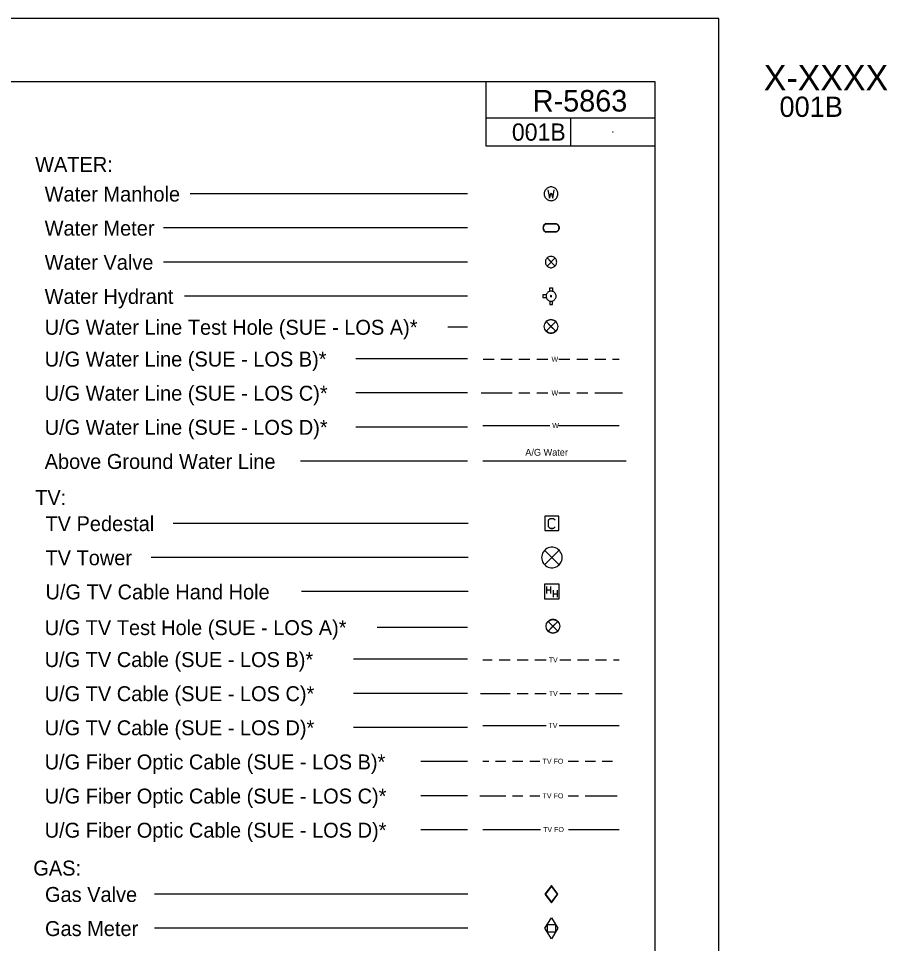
# Model space of a CAD drawing. Extents: x 2040834 to 2047174, y 618431 to 621625.
# Drawn here: x 2046575 to 2047174, y 620986 to 621625 of the extents above; entities that cross this region are included whole.
import ezdxf

# ---------------------------------------------------------------- set-up
doc = ezdxf.new("R2010")
doc.units = 0
for name, color, linetype in [('Default', 7, 'Continuous'), ('Exist Utilities TV Test Hole SUE LOS A CELL', 7, 'Continuous'), ('Exist Utilities Water Test Hole SUE LOS A CELL', 7, 'Continuous')]:
    doc.layers.add(name, color=color, linetype=linetype)

msp = doc.modelspace()

# ---------------------------------------------------------------- linework, layer by layer
at = {"layer": 'Default'}
for p, q in [((2047057.71, 621624.54), (2045074.38, 621624.54)), ((2047057.71, 620341.21), (2047057.71, 621624.54)), ((2047013.96, 621580.79), (2045118.13, 621580.79)), ((2046897.29, 621536.55), (2046897.3, 621580.79)), ((2047013.93, 620384.96), (2047013.96, 621580.79)), ((2047013.96, 621555.8), (2046897.29, 621555.8)), ((2046955.63, 621536.55), (2046955.63, 621555.8)), ((2047013.96, 621536.55), (2046897.29, 621536.55)), ((2046884.38, 621503.62), (2046693.23, 621503.62)), ((2046884.38, 621480.08), (2046674.81, 621480.08)), ((2046938.48, 621483.11), (2046945.71, 621483.11)), ((2046938.48, 621482.87), (2046945.71, 621482.87)), ((2046945.66, 621477.34), (2046938.48, 621477.34)), ((2046945.66, 621477.1), (2046938.48, 621477.1)), ((2046884.38, 621456.54), (2046674.81, 621456.54)), ((2046884.38, 621433), (2046689.23, 621433)), ((2046884.38, 621411.71), (2046870.79, 621411.71)), ((2046884.38, 621389.76), (2046807.42, 621389.76)), ((2046895.18, 621389.51), (2046902.83, 621389.51)), ((2046907.54, 621389.51), (2046915.19, 621389.51)), ((2046919.9, 621389.51), (2046927.55, 621389.51)), ((2046932.26, 621389.51), (2046939.91, 621389.51)), ((2046947.44, 621389.51), (2046955.09, 621389.51)), ((2046959.8, 621389.51), (2046967.45, 621389.51)), ((2046972.16, 621389.51), (2046979.81, 621389.51)), ((2046984.52, 621389.51), (2046989.15, 621389.51)), ((2046884.38, 621366.22), (2046807.42, 621366.22)), ((2046893.84, 621366.22), (2046915.19, 621366.22)), ((2046919.9, 621366.22), (2046927.55, 621366.22)), ((2046932.26, 621366.22), (2046939.91, 621366.22)), ((2046947.44, 621366.22), (2046955.09, 621366.22)), ((2046959.8, 621366.22), (2046967.45, 621366.22)), ((2046972.16, 621366.22), (2046991.36, 621366.22)), ((2046884.38, 621342.68), (2046807.42, 621342.68)), ((2046894.99, 621343.71), (2046941.25, 621343.71)), ((2046947.13, 621343.71), (2046989.15, 621343.71)), ((2046884.38, 621319.14), (2046769.36, 621319.14)), ((2046894.99, 621319.39), (2046993.88, 621319.39)), ((2046884.94, 621276.24), (2046681.4, 621276.24)), ((2046941.89, 621272.77), (2046943.41, 621272.77)), ((2046884.94, 621252.7), (2046666.19, 621252.7)), ((2046884.94, 621229.15), (2046769.92, 621229.15)), ((2046939.03, 621232.72), (2046939.03, 621227.97)), ((2046939.03, 621230.3), (2046941.74, 621230.3)), ((2046941.74, 621232.72), (2046941.74, 621227.97)), ((2046943.55, 621230.13), (2046943.55, 621225.39)), ((2046946.26, 621230.13), (2046946.26, 621225.39)), ((2046943.55, 621227.72), (2046946.26, 621227.72)), ((2046884.38, 621204.51), (2046822.16, 621204.51)), ((2046884.38, 621182.48), (2046805.88, 621182.48)), ((2046894.99, 621182.1), (2046901.55, 621182.1)), ((2046906.26, 621182.1), (2046913.91, 621182.1)), ((2046918.62, 621182.1), (2046926.27, 621182.1)), ((2046930.98, 621182.1), (2046938.63, 621182.1)), ((2046948.04, 621182.1), (2046955.7, 621182.1)), ((2046960.4, 621182.1), (2046968.06, 621182.1)), ((2046972.76, 621182.1), (2046980.41, 621182.1)), ((2046985.12, 621182.1), (2046989.15, 621182.1)), ((2046884.38, 621158.94), (2046805.88, 621158.94)), ((2046893.36, 621158.94), (2046913.91, 621158.94)), ((2046918.62, 621158.94), (2046926.27, 621158.94)), ((2046930.98, 621158.94), (2046938.63, 621158.94)), ((2046948.04, 621158.94), (2046955.7, 621158.94)), ((2046960.4, 621158.94), (2046968.06, 621158.94)), ((2046972.76, 621158.94), (2046991.13, 621158.94)), ((2046884.38, 621135.4), (2046805.88, 621135.4)), ((2046894.99, 621136.83), (2046938.75, 621136.83)), ((2046947.57, 621136.83), (2046989.15, 621136.83)), ((2046884.38, 621111.86), (2046852.32, 621111.86)), ((2046894.99, 621112.14), (2046899.11, 621112.14)), ((2046903.82, 621112.14), (2046910.88, 621112.14)), ((2046915.59, 621112.14), (2046922.65, 621112.14)), ((2046927.36, 621112.14), (2046934.42, 621112.14)), ((2046953.84, 621112.14), (2046960.9, 621112.14)), ((2046965.61, 621112.14), (2046972.68, 621112.14)), ((2046977.38, 621112.14), (2046984.45, 621112.14)), ((2046884.38, 621088.32), (2046852.32, 621088.32)), ((2046893.06, 621088.32), (2046910.88, 621088.32)), ((2046915.59, 621088.32), (2046922.65, 621088.32)), ((2046927.36, 621088.32), (2046934.42, 621088.32)), ((2046953.84, 621088.32), (2046960.9, 621088.32)), ((2046965.61, 621088.32), (2046987.66, 621088.32)), ((2046884.38, 621064.77), (2046852.32, 621064.77)), ((2046894.99, 621065.05), (2046934.76, 621065.05)), ((2046954.18, 621065.05), (2046989.15, 621065.05)), ((2046942.31, 621025.99), (2046938.18, 621020.44)), ((2046946.45, 621020.44), (2046942.31, 621025.99)), ((2046884.62, 621020.44), (2046668.64, 621020.44)), ((2046938.18, 621020.44), (2046942.31, 621014.88)), ((2046942.31, 621014.88), (2046946.45, 621020.44)), ((2046884.62, 620996.89), (2046668.64, 620996.89))]:
    msp.add_line(p, q, dxfattribs=at)
for points in [[(2046942.07, 621508.4), (2046941.46, 621508.37), (2046940.89, 621508.25), (2046940.31, 621508.06), (2046939.78, 621507.79), (2046939.28, 621507.49), (2046938.82, 621507.1), (2046938.4, 621506.65), (2046938.06, 621506.19), (2046937.75, 621505.65), (2046937.56, 621505.08), (2046937.41, 621504.5), (2046937.33, 621503.93), (2046937.33, 621503.32), (2046937.41, 621502.75), (2046937.56, 621502.13), (2046937.75, 621501.6), (2046938.06, 621501.06), (2046938.4, 621500.6), (2046938.82, 621500.15), (2046939.28, 621499.76), (2046939.78, 621499.46), (2046940.31, 621499.19), (2046940.89, 621499), (2046941.5, 621498.88), (2046942.07, 621498.85), (2046942.68, 621498.88), (2046943.26, 621499), (2046943.83, 621499.19), (2046944.36, 621499.46), (2046944.86, 621499.76), (2046945.32, 621500.15), (2046945.74, 621500.6), (2046946.09, 621501.06), (2046946.39, 621501.6), (2046946.58, 621502.17), (2046946.74, 621502.75), (2046946.81, 621503.32), (2046946.81, 621503.93), (2046946.74, 621504.5), (2046946.58, 621505.11), (2046946.39, 621505.65), (2046946.09, 621506.19), (2046945.74, 621506.65), (2046945.32, 621507.1), (2046944.86, 621507.49), (2046944.36, 621507.79), (2046943.83, 621508.06), (2046943.26, 621508.25), (2046942.64, 621508.37), (2046942.07, 621508.4)], [(2046939.93, 621506.26), (2046940.92, 621500.68), (2046942.07, 621504.2), (2046943.26, 621500.68), (2046944.25, 621506.26)], [(2046938.48, 621483.11), (2046938.01, 621482.87), (2046937.58, 621482.54), (2046937.2, 621482.12), (2046936.92, 621481.69), (2046936.68, 621481.17), (2046936.54, 621480.65), (2046936.49, 621480.13), (2046936.54, 621479.56), (2046936.68, 621479.04), (2046936.92, 621478.57), (2046937.2, 621478.1), (2046937.58, 621477.72), (2046938.01, 621477.39), (2046938.48, 621477.1)], [(2046938.57, 621482.92), (2046938.1, 621482.64), (2046937.68, 621482.3), (2046937.3, 621481.88), (2046937.01, 621481.45), (2046936.82, 621480.93), (2046936.73, 621480.37), (2046936.73, 621479.85), (2046936.82, 621479.33), (2046937.01, 621478.81), (2046937.3, 621478.33), (2046937.68, 621477.91), (2046938.1, 621477.58), (2046938.57, 621477.34)], [(2046945.57, 621482.92), (2046946.09, 621482.68), (2046946.51, 621482.3), (2046946.84, 621481.93), (2046947.13, 621481.45), (2046947.32, 621480.93), (2046947.41, 621480.37), (2046947.41, 621479.85), (2046947.32, 621479.28), (2046947.13, 621478.81), (2046946.84, 621478.33), (2046946.47, 621477.91), (2046946.04, 621477.58), (2046945.57, 621477.29)], [(2046945.66, 621483.11), (2046946.14, 621482.87), (2046946.56, 621482.54), (2046946.94, 621482.12), (2046947.22, 621481.69), (2046947.46, 621481.17), (2046947.6, 621480.65), (2046947.65, 621480.13), (2046947.6, 621479.56), (2046947.46, 621479.04), (2046947.22, 621478.57), (2046946.94, 621478.1), (2046946.56, 621477.72), (2046946.14, 621477.39), (2046945.66, 621477.1)], [(2046945.98, 621456.54), (2046945.94, 621457.11), (2046945.81, 621457.71), (2046945.59, 621458.23), (2046945.29, 621458.76), (2046944.94, 621459.19), (2046944.5, 621459.58), (2046944.03, 621459.93), (2046943.5, 621460.19), (2046942.94, 621460.37), (2046942.38, 621460.45), (2046941.77, 621460.45), (2046941.2, 621460.37), (2046940.64, 621460.19), (2046940.11, 621459.93), (2046939.64, 621459.58), (2046939.2, 621459.19), (2046938.86, 621458.76), (2046938.55, 621458.23), (2046938.33, 621457.71), (2046938.2, 621457.11), (2046938.16, 621456.54), (2046938.2, 621455.98), (2046938.33, 621455.37), (2046938.55, 621454.85), (2046938.86, 621454.33), (2046939.2, 621453.89), (2046939.64, 621453.5), (2046940.11, 621453.15), (2046940.64, 621452.89), (2046941.2, 621452.72), (2046941.77, 621452.63), (2046942.38, 621452.63), (2046942.94, 621452.72), (2046943.5, 621452.89), (2046944.03, 621453.15), (2046944.5, 621453.5), (2046944.94, 621453.89), (2046945.29, 621454.33), (2046945.59, 621454.85), (2046945.81, 621455.37), (2046945.94, 621455.98), (2046945.98, 621456.54)], [(2046944.85, 621453.76), (2046939.29, 621459.32), (2046942.07, 621456.54), (2046939.29, 621453.76), (2046944.85, 621459.32)], [(2046938.73, 621433.9), (2046936.47, 621433.9), (2046936.47, 621432.1), (2046938.73, 621432.1)], [(2046942.03, 621436.48), (2046941.48, 621436.43), (2046940.94, 621436.3), (2046940.4, 621436.07), (2046939.95, 621435.76), (2046939.54, 621435.39), (2046939.18, 621434.94), (2046938.91, 621434.45), (2046938.73, 621433.9), (2046938.59, 621433.36), (2046938.59, 621432.82), (2046938.68, 621432.28), (2046938.82, 621431.73), (2046939.09, 621431.24), (2046939.4, 621430.79), (2046939.81, 621430.38), (2046940.26, 621430.02), (2046940.76, 621429.79), (2046941.3, 621429.61), (2046941.85, 621429.52), (2046942.39, 621429.52), (2046942.93, 621429.61), (2046943.47, 621429.84), (2046943.97, 621430.06), (2046944.42, 621430.42), (2046944.78, 621430.83), (2046945.1, 621431.28), (2046945.32, 621431.82), (2046945.5, 621432.37), (2046945.55, 621432.91), (2046945.5, 621433.45), (2046945.41, 621433.99), (2046945.19, 621434.54), (2046944.92, 621435.03), (2046944.56, 621435.44), (2046944.11, 621435.8), (2046943.65, 621436.12), (2046943.11, 621436.3), (2046942.57, 621436.43), (2046942.03, 621436.48)], [(2046941.21, 621436.39), (2046941.21, 621438.65), (2046943.02, 621438.65), (2046943.02, 621436.34)], [(2046942.07, 621433.41), (2046941.89, 621433.36), (2046941.75, 621433.22), (2046941.66, 621433.04), (2046941.71, 621432.86), (2046941.8, 621432.68), (2046941.98, 621432.59), (2046942.16, 621432.59), (2046942.34, 621432.68), (2046942.43, 621432.86), (2046942.48, 621433.04), (2046942.39, 621433.22), (2046942.25, 621433.36), (2046942.07, 621433.41)], [(2046941.21, 621429.61), (2046941.21, 621427.35), (2046943.02, 621427.35), (2046943.02, 621429.66)], [(2046937.73, 621271.33), (2046947.54, 621271.33), (2046947.54, 621281.14), (2046937.73, 621281.14), (2046937.73, 621271.33)], [(2046944.93, 621273.86), (2046943.76, 621272.77), (2046941.5, 621272.77), (2046940.42, 621273.86), (2046940.42, 621278.61), (2046941.5, 621279.7), (2046943.76, 621279.7), (2046944.93, 621278.61)], [(2046949.72, 621252.7), (2046949.64, 621253.72), (2046949.41, 621254.82), (2046949.01, 621255.77), (2046948.46, 621256.71), (2046947.83, 621257.5), (2046947.05, 621258.21), (2046946.18, 621258.84), (2046945.23, 621259.31), (2046944.21, 621259.63), (2046943.19, 621259.79), (2046942.08, 621259.79), (2046941.06, 621259.63), (2046940.03, 621259.31), (2046939.09, 621258.84), (2046938.22, 621258.21), (2046937.44, 621257.5), (2046936.81, 621256.71), (2046936.25, 621255.77), (2046935.86, 621254.82), (2046935.62, 621253.72), (2046935.54, 621252.7), (2046935.62, 621251.67), (2046935.86, 621250.57), (2046936.25, 621249.63), (2046936.81, 621248.68), (2046937.44, 621247.89), (2046938.22, 621247.18), (2046939.09, 621246.55), (2046940.03, 621246.08), (2046941.06, 621245.76), (2046942.08, 621245.61), (2046943.19, 621245.61), (2046944.21, 621245.76), (2046945.23, 621246.08), (2046946.18, 621246.55), (2046947.05, 621247.18), (2046947.83, 621247.89), (2046948.46, 621248.68), (2046949.01, 621249.63), (2046949.41, 621250.57), (2046949.64, 621251.67), (2046949.72, 621252.7)], [(2046947.68, 621247.65), (2046937.59, 621257.74), (2046942.63, 621252.7), (2046937.59, 621247.65), (2046947.68, 621257.74)], [(2046937.57, 621224.09), (2046947.7, 621224.09), (2046947.7, 621234.22), (2046937.57, 621234.22), (2046937.57, 621224.09)], [(2046942.31, 621026.46), (2046937.82, 621020.44), (2046942.31, 621014.41), (2046946.8, 621020.44), (2046942.31, 621026.46)], [(2046937.82, 620996.89), (2046942.31, 621004.16), (2046946.8, 620996.89), (2046942.31, 620989.63), (2046937.82, 620996.89)], [(2046939.53, 620999.61), (2046945.09, 620999.61), (2046945.09, 620994.12), (2046939.53, 620994.12), (2046939.53, 620999.61)]]:
    msp.add_lwpolyline(points, dxfattribs=at)
for centre in [(2046955.63, 621568.3), (2046926.46, 621546.18), (2046984.79, 621546.18), (2046897.29, 621536.55)]:
    msp.add_circle(centre, 0.07, dxfattribs=at)
at = {"layer": 'Exist Utilities TV Test Hole SUE LOS A CELL'}
for points in [[(2046946.7, 621208.58), (2046940.05, 621201.93), (2046943.37, 621205.25), (2046940.05, 621208.58), (2046946.7, 621201.93)], [(2046940.05, 621208.58), (2046943.37, 621205.25), (2046946.7, 621208.58)], [(2046946.7, 621201.93), (2046943.37, 621205.25), (2046940.05, 621201.93)]]:
    msp.add_lwpolyline(points, dxfattribs=at)
msp.add_circle((2046943.37, 621205.25), 4.7, dxfattribs=at)
for start, end in [(45, 135), (225, 315)]:
    msp.add_arc((2046943.37, 621205.25), 4.7, start, end, dxfattribs=at)
at = {"layer": 'Exist Utilities Water Test Hole SUE LOS A CELL'}
for points in [[(2046945.36, 621415.45), (2046938.7, 621408.8), (2046942.03, 621412.12), (2046938.7, 621415.45), (2046945.36, 621408.8)], [(2046938.7, 621415.45), (2046942.03, 621412.12), (2046945.36, 621415.45)], [(2046945.36, 621408.8), (2046942.03, 621412.12), (2046938.7, 621408.8)]]:
    msp.add_lwpolyline(points, dxfattribs=at)
msp.add_circle((2046942.03, 621412.12), 4.7, dxfattribs=at)
for start, end in [(45, 135), (225, 315)]:
    msp.add_arc((2046942.03, 621412.12), 4.7, start, end, dxfattribs=at)

# ---------------------------------------------------------------- texts
at = {"layer": 'Default'}
for s, height, p in [('X-XXXX', 17.5, (2047088.78, 621574.97)), ('R-5863', 14.859, (2046929.46, 621560.34)), ('001B', 14, (2047099.63, 621556.66)), ('001B', 11.887, (2046915.05, 621540.25)), ('WATER:', 10.3, (2046586.25, 621518.74)), ('Water Manhole', 10.2996, (2046592.81, 621498.28)), ('Water Meter', 10.2996, (2046592.81, 621474.74)), ('Water Valve', 10.2996, (2046592.81, 621451.2)), ('Water Hydrant', 10.2996, (2046592.81, 621427.66)), ('U/G Water Line Test Hole (SUE - LOS A)*', 10.2996, (2046592.81, 621406.37)), ('U/G Water Line (SUE - LOS B)*', 10.2996, (2046592.81, 621384.42)), ('W', 3.53, (2046942.38, 621387.74)), ('U/G Water Line (SUE - LOS C)*', 10.2996, (2046592.81, 621360.88)), ('W', 3.53, (2046942.38, 621364.45)), ('U/G Water Line (SUE - LOS D)*', 10.2996, (2046592.81, 621337.34)), ('W', 3.53, (2046942.89, 621341.95)), ('Above Ground Water Line', 10.2996, (2046592.81, 621313.8)), ('A/G Water', 4.708, (2046924.33, 621322.92)), ('TV:', 10.3, (2046586.25, 621288.89)), ('TV Pedestal', 10.2996, (2046593.37, 621270.9)), ('TV Tower', 10.3, (2046593.37, 621247.36)), ('U/G TV Cable Hand Hole', 10.2996, (2046593.37, 621223.81)), ('U/G TV Test Hole (SUE - LOS A)*', 10.2996, (2046592.81, 621199.17)), ('U/G TV Cable (SUE - LOS B)*', 10.2996, (2046592.81, 621177.14)), ('TV', 3.531, (2046940.45, 621180.34)), ('U/G TV Cable (SUE - LOS C)*', 10.2996, (2046592.81, 621153.6)), ('TV', 3.531, (2046940.45, 621157.18)), ('U/G TV Cable (SUE - LOS D)*', 10.2996, (2046592.81, 621130.06)), ('TV', 3.531, (2046940.28, 621135.06)), ('U/G Fiber Optic Cable (SUE - LOS B)*', 10.2996, (2046592.81, 621106.52)), ('TV FO', 3.531, (2046936.24, 621110.38)), ('U/G Fiber Optic Cable (SUE - LOS C)*', 10.2996, (2046592.81, 621082.97)), ('TV FO', 3.531, (2046936.24, 621086.55)), ('U/G Fiber Optic Cable (SUE - LOS D)*', 10.2996, (2046592.81, 621059.43)), ('TV FO', 3.531, (2046936.58, 621063.29)), ('GAS:', 10.3, (2046584.97, 621033.3)), ('Gas Valve', 10.3, (2046593.05, 621015.09)), ('Gas Meter', 10.3, (2046593.05, 620991.55))]:
    msp.add_text(s, height=height, dxfattribs=at).set_placement(p)

doc.saveas('drawing.dxf')
